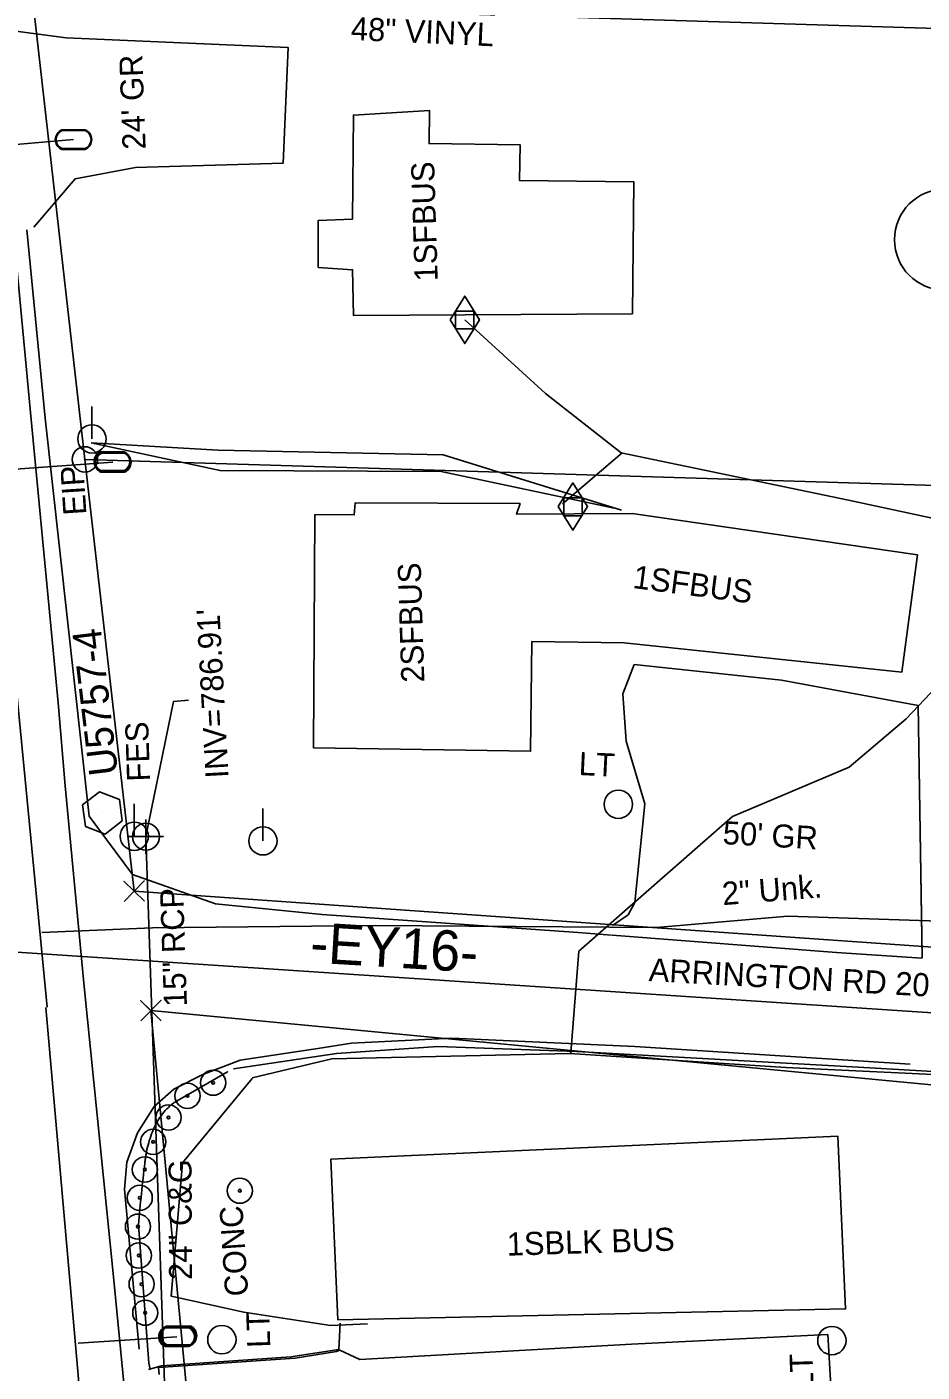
# Model space of a CAD drawing. Extents: x 1627482 to 1629573, y 760826 to 766301.
# Drawn here: x 1628290.6 to 1628445.9, y 765527.6 to 765761 of the extents above; entities that cross this region are included whole.
import ezdxf

# ---------------------------------------------------------------- set-up
doc = ezdxf.new("R2010")
doc.units = 0
for name, color, linetype in [('CTL Primary Horizontal and Vertical CELL', 7, 'Continuous'), ('CTL Primary Horizontal and Vertical Text', 7, 'Continuous'), ('Default', 7, 'Continuous'), ('Exist Building', 7, 'Continuous'), ('Exist Building Leader', 7, 'Continuous'), ('Exist Building Text', 7, 'Continuous'), ('Exist Horizontal Alignment', 7, 'Continuous'), ('Exist Horizontal Alignment Direction Label', 7, 'Continuous'), ('Exist Other Culture Fence Line Text', 7, 'Continuous'), ('Exist Other Culture Located Object CELL', 7, 'Continuous'), ('Exist Other Culture Sign CELL', 7, 'Continuous'), ('Exist Property Corner CELL', 7, 'Continuous'), ('Exist Property Iron Pin CELL', 7, 'Continuous'), ('Exist Property Iron Pin Text', 7, 'Continuous'), ('Exist Property Line', 7, 'Continuous'), ('Exist Property Owner Number CELL', 7, 'Continuous'), ('Exist Right of Way Line', 7, 'Continuous'), ('Exist Roads Change in Surface', 7, 'Continuous'), ('Exist Roads Curbs', 7, 'Continuous'), ('Exist Roads Curbs Text', 7, 'Continuous'), ('Exist Roads EOP', 7, 'Continuous'), ('Exist Roads EOP Other', 7, 'Continuous'), ('Exist Roads EOP Other Text', 7, 'Continuous'), ('Exist Roads EOP Text', 7, 'Continuous'), ('Exist Roads EOT', 7, 'Continuous'), ('Exist Roads Soil', 7, 'Continuous'), ('Exist Roads Soil Text', 7, 'Continuous'), ('Exist Structure Minor Pipes RCP 12 Inch Cogo Point CELL', 7, 'Continuous'), ('Exist Structure Minor Pipes RCP 12 Inch Invert', 7, 'Continuous'), ('Exist Structure Minor Pipes RCP 12 Inch Leader', 7, 'Continuous'), ('Exist Structure Minor Pipes RCP 15 Inch', 7, 'Continuous'), ('Exist Structure Minor Pipes RCP 15 Inch Text', 7, 'Continuous'), ('Exist Utilities Gas Meter CELL', 7, 'Continuous'), ('Exist Utilities Gas UG Line SUE LOS B', 7, 'Continuous'), ('Exist Utilities Other Pole CELL', 7, 'Continuous'), ('Exist Utilities Other Pole Text', 7, 'Continuous'), ('Exist Utilities Power Pole CELL', 7, 'Continuous'), ('Exist Utilities Power UG Cable SUE LOS B', 7, 'Continuous'), ('Exist Utilities Telephone UG Cable SUE LOS B', 7, 'Continuous'), ('Exist Utilities Water Meter CELL', 7, 'Continuous'), ('Exist Utilities Water UG Line SUE LOS B', 7, 'Continuous'), ('Exist Utilities Water UG Line SUE LOS B Text', 7, 'Continuous')]:
    doc.layers.add(name, color=color, linetype=linetype)

# ---------------------------------------------------------------- blocks, each defined once
blk = doc.blocks.new('EXIST PROPERTY IRON PIN_368')
at = {"layer": 'Exist Property Iron Pin CELL'}
for radius in [3.36, 0.108]:
    blk.add_circle((0, 0), radius, dxfattribs=at)
blk = doc.blocks.new('POINT_DISPLAY')
at = {"layer": 'Default'}
blk.add_line((0, 0), (0, 0), dxfattribs=at)
blk = doc.blocks.new('EXIST PROPERTY CORNER')
at = {"layer": 'Exist Property Corner CELL'}
blk.add_lwpolyline([(-3.81, 0), (3.81, 0), (0, 0), (0, 3.81), (0, -3.81)], dxfattribs=at)
blk.add_blockref('POINT_DISPLAY', (0, 0), dxfattribs=at)

msp = doc.modelspace()

# ---------------------------------------------------------------- linework, layer by layer
at = {"layer": 'CTL Primary Horizontal and Vertical CELL'}
msp.add_line((1628303.72, 765624.63), (1628303.72, 765624.63), dxfattribs=at)
msp.add_lwpolyline([(1628300.26, 765626.03), (1628303.22, 765628.28), (1628306.69, 765626.96), (1628307.16, 765623.27), (1628304.21, 765620.94), (1628300.79, 765622.29)], close=True, dxfattribs=at)
at = {"layer": 'Exist Building'}
for points in [[(1628395.66, 765711.23), (1628395.92, 765734.09), (1628376.09, 765734.32), (1628376.17, 765740.56), (1628360.39, 765740.74), (1628360.46, 765746.52), (1628347.26, 765745.7), (1628347.1, 765727.63), (1628341.15, 765727.43), (1628341.15, 765719.28), (1628347.12, 765718.87), (1628347.26, 765710.93)], [(1628340.56, 765676.43), (1628347.41, 765676.33), (1628347.59, 765678.45), (1628376.18, 765678.29), (1628375.55, 765676.48), (1628395.59, 765676.56), (1628445.14, 765669.39), (1628442.38, 765649.03), (1628394.23, 765654.16), (1628378.24, 765654.36), (1628378, 765635.35), (1628340.35, 765635.91)], [(1628343.36, 765564.6), (1628431.28, 765568.58), (1628432.63, 765538.59), (1628344.56, 765536.7)]]:
    msp.add_lwpolyline(points, close=True, dxfattribs=at)
at = {"layer": 'Exist Building Leader'}
msp.add_line((1628340.77, 765664.59), (1628340.77, 765664.59), dxfattribs=at)
at = {"layer": 'Exist Horizontal Alignment'}
msp.add_line((1628281, 765601.01), (1628622.86, 765578.3), dxfattribs=at)
at = {"layer": 'Exist Other Culture Located Object CELL'}
for centre, radius in [((1628322.93, 765577.83), 2.18), ((1628318.48, 765575.56), 2.18), ((1628322.93, 765577.83), 0.24), ((1628318.48, 765575.56), 0.24), ((1628315.18, 765571.8), 2.18), ((1628315.18, 765571.8), 0.24), ((1628312.52, 765567.57), 2.18), ((1628312.52, 765567.57), 0.24), ((1628311.08, 765562.78), 2.18), ((1628311.08, 765562.78), 0.24), ((1628310.2, 765557.86), 2.18), ((1628310.2, 765557.86), 0.24), ((1628309.89, 765552.87), 2.18), ((1628309.89, 765552.87), 0.24), ((1628310.04, 765547.87), 2.18), ((1628310.04, 765547.87), 0.24), ((1628310.52, 765542.89), 2.18), ((1628310.52, 765542.89), 0.24), ((1628311.15, 765537.93), 2.18), ((1628311.15, 765537.93), 0.24)]:
    msp.add_circle(centre, radius, dxfattribs=at)
at = {"layer": 'Exist Other Culture Sign CELL'}
for radius in [2.18, 0.24]:
    msp.add_circle((1628327.56, 765559.1), radius, dxfattribs=at)
at = {"layer": 'Exist Property Line'}
for points in [[(1628291.67, 765765.52), (1628539.17, 765757.93), (1628546.85, 765678.42)], [(1628300.68, 765685.97), (1628546.85, 765678.42), (1628555.03, 765593.82)]]:
    msp.add_lwpolyline(points, dxfattribs=at)
at = {"layer": 'Exist Property Owner Number CELL'}
msp.add_circle((1628449.87, 765724.09), 8.75, dxfattribs=at)
at = {"layer": 'Exist Right of Way Line'}
for p in [(1628552.22, 765567.5), (1628319.06, 765517.02)]:
    msp.add_line(p, (1628312.14, 765590.34), dxfattribs=at)
for points in [[(1628300.68, 765685.97), (1628291.67, 765765.52)], [(1628555.03, 765593.82), (1628309.24, 765611.05), (1628300.68, 765685.97)]]:
    msp.add_lwpolyline(points, dxfattribs=at)
at = {"layer": 'Exist Roads Change in Surface'}
msp.add_lwpolyline([(1628445.84, 765599.45), (1628431.07, 765600.44), (1628392.14, 765603.43)], dxfattribs=at)
at = {"layer": 'Exist Roads Curbs'}
for points in [[(1628316.67, 765574.68), (1628316.67, 765574.68), (1628325.4, 765579.75), (1628325.46, 765579.8)], [(1628312.01, 765528.15), (1628311.8, 765529.21), (1628309.97, 765553.19)]]:
    msp.add_lwpolyline(points, dxfattribs=at)
msp.add_spline([(1628309.97, 765553.19), (1628311.08, 765563.92), (1628311.18, 765564.69), (1628311.3, 765565.46), (1628311.64, 765567.02), (1628312.72, 765570.06), (1628314.38, 765572.72), (1628315.44, 765573.81), (1628316.03, 765574.28), (1628316.67, 765574.68)], degree=3, dxfattribs=at)
at = {"layer": 'Exist Roads EOP'}
for p, q in [((1628308.96, 765613.97), (1628301.4, 765624.06)), ((1628310.11, 765531.62), (1628307.55, 765559.36))]:
    msp.add_line(p, q, dxfattribs=at)
for points in [[(1628301.4, 765624.06), (1628293.77, 765693.11), (1628290.63, 765725.8)], [(1628392.03, 765603.44), (1628386.24, 765603.88), (1628341.82, 765607.03), (1628323.35, 765608.87), (1628308.96, 765613.97)], [(1628621.99, 765569.23), (1628577.18, 765572.31), (1628524.59, 765575.74), (1628479.76, 765577.95), (1628434.85, 765580.56), (1628385.94, 765583.27), (1628361.89, 765584.09), (1628344.34, 765582.92), (1628326.47, 765580.25)], [(1628313.56, 765527.24), (1628313.45, 765528.44), (1628337.13, 765530.05), (1628344.34, 765531.22), (1628344.88, 765531.43), (1628348.38, 765529.81), (1628395.48, 765532.47), (1628429.55, 765534.14), (1628431.63, 765498.39), (1628432.57, 765475.59), (1628433.34, 765464.02), (1628452.44, 765463.49)]]:
    msp.add_lwpolyline(points, dxfattribs=at)
at = {"layer": 'Exist Roads EOP Other'}
for points in [[(1628307.55, 765559.36), (1628307.97, 765564.05), (1628309.82, 765569.17), (1628312.71, 765573.71), (1628316.13, 765576.73), (1628321.15, 765579.25), (1628327.63, 765581.77), (1628341.07, 765583.78), (1628346.91, 765584.67)], [(1628443.82, 765581.06), (1628396.08, 765584.11), (1628364.36, 765585.55), (1628346.91, 765584.67)], [(1628311.72, 765528.06), (1628313.98, 765528.73), (1628336.42, 765530.31), (1628344.76, 765531.56), (1628344.96, 765536.11)]]:
    msp.add_lwpolyline(points, dxfattribs=at)
at = {"layer": 'Exist Roads EOT'}
msp.add_lwpolyline([(1628333.52, 765248.4), (1628329.4, 765298.18), (1628324.72, 765348.12), (1628319.83, 765396.83), (1628315.15, 765446.04), (1628310.38, 765495.44), (1628305.6, 765544.74), (1628300.53, 765594.55), (1628297.28, 765629.36), (1628296.07, 765643.72), (1628291.37, 765692.86), (1628286.71, 765742.17), (1628281.97, 765791.57), (1628277.28, 765840.65), (1628272.47, 765890.08), (1628267.44, 765941.93), (1628262.71, 765991.13), (1628257.98, 766041.68), (1628253.31, 766091.45), (1628248.62, 766139.51)], dxfattribs=at)
at = {"layer": 'Exist Roads Soil'}
for points in [[(1628288.7, 765760.25), (1628297.41, 765759.08), (1628335.94, 765757.44), (1628335.09, 765737.37), (1628309.47, 765736.61), (1628298.98, 765734.66), (1628291.8, 765726.27)], [(1628392.19, 765605.08), (1628394.9, 765606.96), (1628396.07, 765609.12), (1628397.83, 765626.21), (1628394.6, 765637.09), (1628393.99, 765645.27), (1628395.99, 765650.36), (1628421.53, 765647.66), (1628445.22, 765643.3), (1628445.91, 765599.44)], [(1628392.19, 765605.08), (1628394.9, 765606.96), (1628396.07, 765609.12), (1628397.83, 765626.21), (1628394.6, 765637.09), (1628393.99, 765645.27), (1628395.99, 765650.36), (1628421.53, 765647.66), (1628445.22, 765643.3), (1628445.91, 765599.61)]]:
    msp.add_lwpolyline(points, dxfattribs=at)
at = {"layer": 'Exist Structure Minor Pipes RCP 12 Inch Cogo Point CELL'}
msp.add_lwpolyline([(1628311.28, 765623.52), (1628311.28, 765617.52), (1628311.28, 765620.52), (1628314.28, 765620.52), (1628308.28, 765620.52)], dxfattribs=at)
msp.add_circle((1628311.28, 765620.52), 2.34, dxfattribs=at)
at = {"layer": 'Exist Structure Minor Pipes RCP 12 Inch Leader'}
msp.add_lwpolyline([(1628311.28, 765620.52), (1628316.07, 765643.95), (1628318.66, 765644.19)], dxfattribs=at)
at = {"layer": 'Exist Structure Minor Pipes RCP 15 Inch'}
msp.add_line((1628316.06, 765478.93), (1628311.28, 765620.52), dxfattribs=at)
at = {"layer": 'Exist Utilities Gas Meter CELL'}
for p, q in [((1628366.58, 765710.17), (1628366.58, 765710.17)), ((1628385.35, 765677.78), (1628385.35, 765677.78))]:
    msp.add_line(p, q, dxfattribs=at)
for points in [[(1628364.04, 765710.17), (1628366.58, 765714.29), (1628369.12, 765710.17), (1628366.58, 765706.06), (1628364.04, 765710.17)], [(1628365, 765711.71), (1628368.15, 765711.71), (1628368.15, 765708.6), (1628365, 765708.6), (1628365, 765711.71)], [(1628382.81, 765677.78), (1628385.35, 765681.89), (1628387.88, 765677.78), (1628385.35, 765673.67), (1628382.81, 765677.78)], [(1628383.77, 765679.32), (1628386.92, 765679.32), (1628386.92, 765676.2), (1628383.77, 765676.2), (1628383.77, 765679.32)]]:
    msp.add_lwpolyline(points, dxfattribs=at)
at = {"layer": 'Exist Utilities Gas UG Line SUE LOS B'}
msp.add_line((1628383.55, 765678.25), (1628393.86, 765687.12), dxfattribs=at)
for points in [[(1628384.96, 765583), (1628386.35, 765600.64), (1628413.04, 765624.04), (1628433.28, 765632.57), (1628443.16, 765640.97), (1628451.66, 765649.9), (1628453.32, 765674.57), (1628433.15, 765678.89), (1628393.69, 765687.11), (1628380.6, 765697.41), (1628366.58, 765710.19)], [(1628456.34, 765578.87), (1628422.28, 765580.5), (1628384.78, 765582.88), (1628343.49, 765581.95), (1628329.71, 765578.7)], [(1628329.7, 765578.59), (1628317.63, 765563.94), (1628315.65, 765540.78), (1628328.26, 765538.04), (1628343.31, 765535.7), (1628349.69, 765535.99)]]:
    msp.add_lwpolyline(points, dxfattribs=at)
at = {"layer": 'Exist Utilities Other Pole CELL'}
for centre in [(1628393.22, 765626.14), (1628324.44, 765533.27), (1628430.26, 765533.1)]:
    msp.add_circle(centre, 2.46, dxfattribs=at)
at = {"layer": 'Exist Utilities Power Pole CELL'}
for p, q in [((1628301.91, 765689.52), (1628301.91, 765695.14)), ((1628301.91, 765689.52), (1628301.91, 765689.52)), ((1628309.24, 765620.59), (1628309.24, 765626.21)), ((1628331.57, 765619.79), (1628331.57, 765625.42)), ((1628309.24, 765620.59), (1628309.24, 765620.59)), ((1628331.57, 765619.79), (1628331.57, 765619.79))]:
    msp.add_line(p, q, dxfattribs=at)
for centre in [(1628301.91, 765689.52), (1628309.24, 765620.59), (1628331.57, 765619.79)]:
    msp.add_circle(centre, 2.45, dxfattribs=at)
at = {"layer": 'Exist Utilities Power UG Cable SUE LOS B'}
msp.add_lwpolyline([(1628301.81, 765688.82), (1628323.82, 765687.55), (1628362.84, 765686.75), (1628393.76, 765677.16)], dxfattribs=at)
at = {"layer": 'Exist Utilities Telephone UG Cable SUE LOS B'}
msp.add_lwpolyline([(1628301.79, 765688.86), (1628324.13, 765684.04), (1628362.46, 765683.86), (1628392.52, 765677.5)], dxfattribs=at)
at = {"layer": 'Exist Utilities Water Meter CELL'}
for p, q in [((1628298.72, 765741.45), (1628298.72, 765741.45)), ((1628305.44, 765685.59), (1628305.44, 765685.59)), ((1628305.54, 765685.46), (1628305.54, 765685.46)), ((1628316.64, 765533.77), (1628316.64, 765533.77)), ((1628316.94, 765533.93), (1628316.94, 765533.93))]:
    msp.add_line(p, q, dxfattribs=at)
for points in [[(1628296.68, 765743.15), (1628300.75, 765743.15)], [(1628296.68, 765743.01), (1628300.75, 765743.01)], [(1628300.75, 765739.88), (1628296.65, 765739.88)], [(1628300.75, 765739.75), (1628296.65, 765739.75)], [(1628303.4, 765687.29), (1628307.47, 765687.29)], [(1628303.4, 765687.16), (1628307.47, 765687.16)], [(1628303.5, 765687.16), (1628307.57, 765687.16)], [(1628303.5, 765687.02), (1628307.57, 765687.02)], [(1628307.47, 765684.03), (1628303.37, 765684.03)], [(1628307.47, 765683.89), (1628303.37, 765683.89)], [(1628307.57, 765683.9), (1628303.47, 765683.9)], [(1628307.57, 765683.76), (1628303.47, 765683.76)], [(1628314.61, 765535.47), (1628318.68, 765535.47)], [(1628314.61, 765535.33), (1628318.68, 765535.33)], [(1628314.9, 765535.63), (1628318.98, 765535.63)], [(1628314.9, 765535.5), (1628318.98, 765535.5)], [(1628318.68, 765532.2), (1628314.58, 765532.2)], [(1628318.68, 765532.07), (1628314.58, 765532.07)], [(1628318.98, 765532.37), (1628314.88, 765532.37)], [(1628318.98, 765532.23), (1628314.88, 765532.23)]]:
    msp.add_lwpolyline(points, dxfattribs=at)
for centre, radius, start, end in [((1628297.41, 765741.44), 1.86, 113.178, 245.9794), ((1628297.42, 765741.44), 1.73, 115.3009, 243.7824), ((1628300.01, 765741.45), 1.86, 293.6483, 66.3084), ((1628300.02, 765741.45), 1.73, 295.1272, 64.8728), ((1628304.13, 765685.59), 1.86, 113.178, 245.9794), ((1628304.23, 765685.45), 1.86, 113.178, 245.9794), ((1628304.14, 765685.59), 1.73, 115.3009, 243.7824), ((1628304.24, 765685.45), 1.73, 115.3009, 243.7824), ((1628306.73, 765685.59), 1.86, 293.6483, 66.3084), ((1628306.74, 765685.59), 1.73, 295.1272, 64.8728), ((1628306.83, 765685.46), 1.86, 293.6483, 66.3084), ((1628306.84, 765685.46), 1.73, 295.1272, 64.8728), ((1628315.34, 765533.76), 1.86, 113.178, 245.9794), ((1628315.35, 765533.76), 1.73, 115.3009, 243.7824), ((1628315.63, 765533.93), 1.86, 113.178, 245.9794), ((1628315.65, 765533.93), 1.73, 115.3009, 243.7824), ((1628317.94, 765533.77), 1.86, 293.6483, 66.3084), ((1628317.95, 765533.77), 1.73, 295.1272, 64.8728), ((1628318.23, 765533.94), 1.86, 293.6483, 66.3084), ((1628318.25, 765533.93), 1.73, 295.1272, 64.8728)]:
    msp.add_arc(centre, radius, start, end, dxfattribs=at)
at = {"layer": 'Exist Utilities Water UG Line SUE LOS B'}
for p, q in [((1628298.72, 765741.45), (1628280.3, 765739.83)), ((1628305.54, 765685.46), (1628285.23, 765684.04)), ((1628316.64, 765533.77), (1628299.54, 765532.66))]:
    msp.add_line(p, q, dxfattribs=at)
for points in [[(1628294.12, 765590.95), (1628282.81, 765707.64), (1628280.41, 765734.76), (1628271.11, 765833.3), (1628263.6, 765911.74), (1628254.6, 766012.23), (1628242.81, 766147.74), (1628234.17, 766229.92), (1628225.44, 766301.43)], [(1628293.23, 765603.87), (1628312.41, 765604.69), (1628351.02, 765605.09), (1628399.83, 765604.77), (1628422.65, 765606.71), (1628459.44, 765605.51), (1628470.42, 765605.41)], [(1628303.42, 765478.68), (1628299.6, 765526.49), (1628293.92, 765590.89)]]:
    msp.add_lwpolyline(points, dxfattribs=at)

# ---------------------------------------------------------------- block references
at = {"layer": 'Exist Property Corner CELL', "xscale": 0.6561666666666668, "yscale": 0.6561666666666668, "rotation": 45.72460018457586}
for p in [(1628309.24, 765611.05), (1628312.14, 765590.34)]:
    msp.add_blockref('EXIST PROPERTY CORNER', p, dxfattribs=at)
at = {"layer": 'Exist Property Iron Pin CELL', "xscale": 0.6561666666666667, "yscale": 0.6561666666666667}
msp.add_blockref('EXIST PROPERTY IRON PIN_368', (1628300.68, 765685.97), dxfattribs=at)

# ---------------------------------------------------------------- texts
at = {"layer": 'CTL Primary Horizontal and Vertical Text'}
msp.add_text('U5757-4', height=5, rotation=96.817, dxfattribs=at).set_placement((1628306.45, 765631.4))
at = {"layer": 'Exist Building Text'}
for s, rotation, p in [('1SFBUS', 91.7713, (1628361.9, 765716.89)), ('2SFBUS', 91.7713, (1628359.58, 765647.32)), ('1SFBUS', 352.5532, (1628395.6, 765663.67)), ('1SBLK BUS', 1.7713, (1628373.93, 765547.82))]:
    msp.add_text(s, height=4, rotation=rotation, dxfattribs=at).set_placement(p)
at = {"layer": 'Exist Horizontal Alignment Direction Label'}
msp.add_text('-EY16-', height=7, rotation=356.5534, dxfattribs=at).set_placement((1628339.63, 765598.7))
at = {"layer": 'Exist Other Culture Fence Line Text'}
msp.add_text('48" VINYL', height=4, rotation=357.4439, dxfattribs=at).set_placement((1628346.76, 765758.73))
at = {"layer": 'Exist Property Iron Pin Text'}
msp.add_text('EIP', height=4, rotation=93.7271, dxfattribs=at).set_placement((1628300.96, 765676.41))
at = {"layer": 'Exist Roads Curbs Text'}
msp.add_text('24" C&G', height=4, rotation=90.2973, dxfattribs=at).set_placement((1628319.28, 765543.64))
at = {"layer": 'Exist Roads EOP Other Text'}
msp.add_text('CONC', height=4, rotation=93.7859, dxfattribs=at).set_placement((1628329.04, 765540.91))
at = {"layer": 'Exist Roads EOP Text'}
msp.add_text("ARRINGTON RD 20' PAVED ROADWAY", height=4, rotation=356.8305, dxfattribs=at).set_placement((1628398.43, 765595.47))
at = {"layer": 'Exist Roads Soil Text'}
for s, rotation, p in [("24' GR", 92.0884, (1628311.23, 765739.78)), ("50' GR", 356.7204, (1628411.25, 765619.24))]:
    msp.add_text(s, height=4, rotation=rotation, dxfattribs=at).set_placement(p)
at = {"layer": 'Exist Structure Minor Pipes RCP 12 Inch Invert'}
msp.add_text("INV=786.91'", height=4, rotation=93.1228, dxfattribs=at).set_placement((1628325.62, 765630.75))
at = {"layer": 'Exist Structure Minor Pipes RCP 15 Inch Text'}
for s, p in [('FES', (1628312, 765630.15)), ('15" RCP', (1628318.4, 765591.07))]:
    msp.add_text(s, height=4, rotation=91.9339, dxfattribs=at).set_placement(p)
at = {"layer": 'Exist Utilities Other Pole Text'}
for rotation, p in [(357.2773, (1628386.28, 765631.22)), (91.7713, (1628332.85, 765531.91)), (91.7713, (1628427.1, 765524.67))]:
    msp.add_text('LT', height=4, rotation=rotation, dxfattribs=at).set_placement(p)
at = {"layer": 'Exist Utilities Water UG Line SUE LOS B Text'}
msp.add_text('2" Unk.', height=4, rotation=4.5128, dxfattribs=at).set_placement((1628411.37, 765608.63))

doc.saveas('drawing.dxf')
